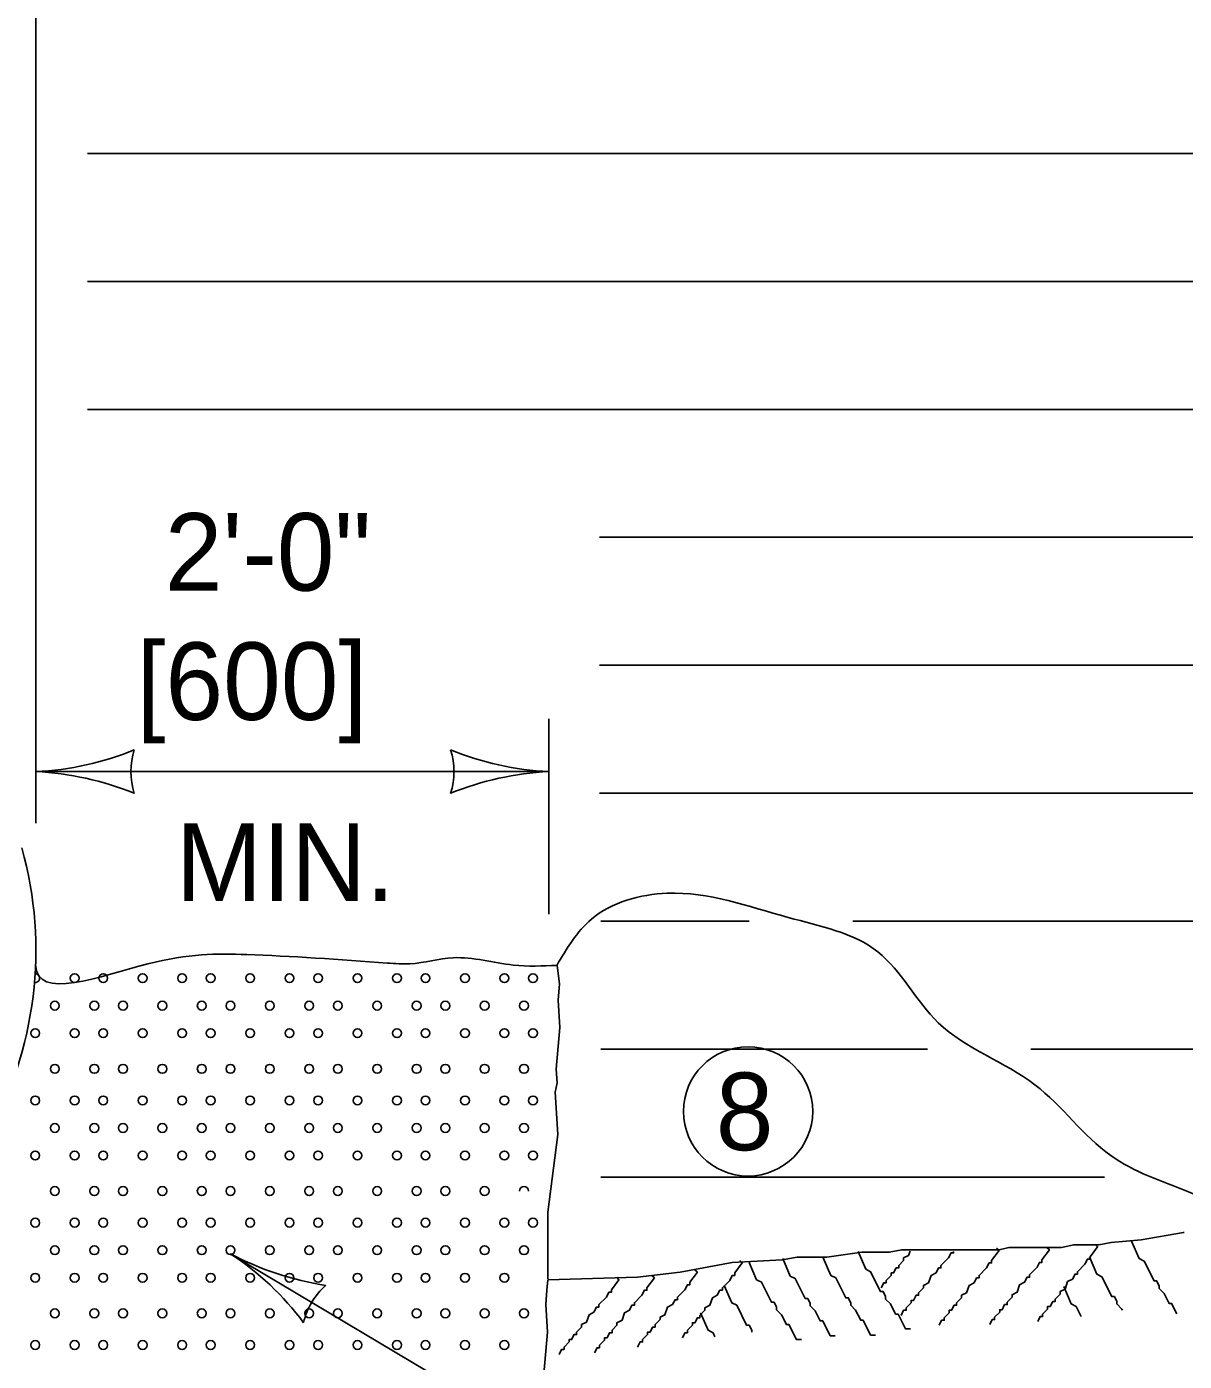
# Model space of a CAD drawing. Extents: x 49991.4 to 50021, y 49987.6 to 50011.4.
# Drawn here: x 50013.69 to 50014.585, y 50002.057 to 50003.09 of the extents above; entities that cross this region are included whole.
import ezdxf

# ---------------------------------------------------------------- set-up
doc = ezdxf.new("R2010")
doc.units = 0
for name, color, linetype in [('Level 1', 7, 'Continuous'), ('Level 2', 7, 'Continuous'), ('Level 3', 7, 'Continuous')]:
    doc.layers.add(name, color=color, linetype=linetype)

msp = doc.modelspace()

# ---------------------------------------------------------------- linework, layer by layer
at = {"layer": 'Level 1'}
for p, q in [((50016.3368, 50002.9916), (50013.737, 50002.9916)), ((50013.737, 50002.8926), (50016.3368, 50002.8926)), ((50013.737, 50002.7936), (50016.3368, 50002.7936)), ((50014.133, 50002.6946), (50016.3368, 50002.6946)), ((50014.133, 50002.5956), (50016.3368, 50002.5956)), ((50014.133, 50002.4966), (50016.3368, 50002.4966)), ((50014.1341, 50002.3976), (50014.2488, 50002.3976)), ((50014.3288, 50002.3976), (50016.3368, 50002.3976)), ((50014.1341, 50002.2986), (50014.3866, 50002.2986)), ((50014.4666, 50002.2986), (50016.3368, 50002.2986)), ((50014.1341, 50002.1996), (50014.5237, 50002.1996))]:
    msp.add_line(p, q, dxfattribs=at)
for points in [[(50014.0931, 50002.1208), (50014.093, 50002.1725), (50014.1007, 50002.2325), (50014.0986, 50002.2653), (50014.1002, 50002.2725), (50014.0994, 50002.2832), (50014.1024, 50002.3154), (50014.101, 50002.3366), (50014.1019, 50002.349), (50014.1002, 50002.3634)], [(50014.093, 50002.1201), (50014.1624, 50002.1221), (50014.1953, 50002.126), (50014.2357, 50002.1336), (50014.2743, 50002.1356), (50014.2858, 50002.1375), (50014.3089, 50002.1375), (50014.336, 50002.1414), (50014.3571, 50002.1414), (50014.3668, 50002.1433), (50014.4111, 50002.1433), (50014.442, 50002.1433), (50014.4497, 50002.1452), (50014.4902, 50002.1452), (50014.4998, 50002.1472), (50014.5191, 50002.1472), (50014.5287, 50002.1491), (50014.5519, 50002.151), (50014.5846, 50002.1568), (50014.5852, 50002.1568)], [(50014.3331, 50002.1419), (50014.3389, 50002.1284), (50014.3427, 50002.1264), (50014.3504, 50002.111), (50014.3524, 50002.111), (50014.3543, 50002.1071), (50014.3543, 50002.1052), (50014.3581, 50002.1014), (50014.362, 50002.0936), (50014.3639, 50002.0936), (50014.3697, 50002.0821), (50014.3736, 50002.0821)], [(50014.3732, 50002.1422), (50014.3721, 50002.139), (50014.3682, 50002.137), (50014.3682, 50002.1351), (50014.3644, 50002.1313), (50014.3644, 50002.1293), (50014.3625, 50002.1293), (50014.3605, 50002.1255), (50014.3586, 50002.1255), (50014.3586, 50002.1235), (50014.3548, 50002.1197), (50014.3548, 50002.1178), (50014.3528, 50002.1178), (50014.3509, 50002.1139)], [(50014.4068, 50002.1419), (50014.4068, 50002.1409), (50014.4049, 50002.1409), (50014.403, 50002.137), (50014.3971, 50002.1313), (50014.3971, 50002.1293), (50014.3952, 50002.1293), (50014.3933, 50002.1255), (50014.3895, 50002.1235), (50014.3875, 50002.1178), (50014.3837, 50002.1158), (50014.3837, 50002.1139), (50014.3798, 50002.1101), (50014.3798, 50002.1081), (50014.3779, 50002.1081), (50014.3759, 50002.1042), (50014.374, 50002.1042), (50014.374, 50002.1023), (50014.3702, 50002.0985), (50014.3702, 50002.0965), (50014.3682, 50002.0965), (50014.3663, 50002.0926)], [(50014.4401, 50002.1447), (50014.442, 50002.1428), (50014.4362, 50002.1351), (50014.4362, 50002.1332), (50014.4343, 50002.1332), (50014.4324, 50002.1293), (50014.4266, 50002.1235), (50014.4266, 50002.1216), (50014.4247, 50002.1216), (50014.4227, 50002.1178), (50014.4189, 50002.1158), (50014.4169, 50002.1101), (50014.4131, 50002.1081), (50014.4131, 50002.1062), (50014.4092, 50002.1023), (50014.4092, 50002.1004), (50014.4073, 50002.1004), (50014.4053, 50002.0965), (50014.4034, 50002.0965), (50014.4034, 50002.0946), (50014.3996, 50002.0907), (50014.3996, 50002.0888), (50014.3976, 50002.0888), (50014.3957, 50002.085)], [(50014.4791, 50002.1452), (50014.481, 50002.1433), (50014.4752, 50002.1356), (50014.4752, 50002.1336), (50014.4733, 50002.1336), (50014.4714, 50002.1298), (50014.4656, 50002.124), (50014.4656, 50002.1221), (50014.4637, 50002.1221), (50014.4618, 50002.1182), (50014.4579, 50002.1163), (50014.456, 50002.1105), (50014.4521, 50002.1086), (50014.4521, 50002.1067), (50014.4483, 50002.1028), (50014.4483, 50002.1009), (50014.4463, 50002.1009), (50014.4444, 50002.097), (50014.4425, 50002.097), (50014.4425, 50002.0951), (50014.4386, 50002.0913), (50014.4386, 50002.0893), (50014.4367, 50002.0893), (50014.4348, 50002.0854)], [(50014.5162, 50002.1476), (50014.5182, 50002.1457), (50014.5124, 50002.138), (50014.5124, 50002.1361), (50014.5104, 50002.1361), (50014.5085, 50002.1322), (50014.5027, 50002.1264), (50014.5027, 50002.1245), (50014.5008, 50002.1245), (50014.4988, 50002.1206), (50014.495, 50002.1187), (50014.4931, 50002.1129), (50014.4892, 50002.111), (50014.4892, 50002.1091), (50014.4853, 50002.1052), (50014.4853, 50002.1033), (50014.4835, 50002.1033), (50014.4815, 50002.0995), (50014.4796, 50002.0995), (50014.4796, 50002.0975), (50014.4757, 50002.0936), (50014.4757, 50002.0917), (50014.4738, 50002.0917), (50014.4719, 50002.0878)], [(50014.5446, 50002.15), (50014.5505, 50002.1365), (50014.5543, 50002.1346), (50014.562, 50002.1192), (50014.5639, 50002.1192), (50014.5658, 50002.1154), (50014.5658, 50002.1134), (50014.5697, 50002.1096), (50014.5736, 50002.1019), (50014.5755, 50002.1019), (50014.5795, 50002.0937)], [(50014.2415, 50002.1351), (50014.2434, 50002.1332), (50014.2376, 50002.1255), (50014.2376, 50002.1235), (50014.2357, 50002.1235), (50014.2338, 50002.1197), (50014.228, 50002.1139), (50014.228, 50002.112), (50014.2261, 50002.112), (50014.2241, 50002.1081), (50014.2203, 50002.1062), (50014.2183, 50002.1004), (50014.2145, 50002.0985), (50014.2145, 50002.0965), (50014.2106, 50002.0926), (50014.2106, 50002.0907), (50014.2087, 50002.0907), (50014.2068, 50002.0869), (50014.2049, 50002.0869), (50014.2049, 50002.085), (50014.201, 50002.0811), (50014.201, 50002.0792), (50014.1991, 50002.0792), (50014.1972, 50002.0753)], [(50014.2487, 50002.1336), (50014.2545, 50002.1201), (50014.2583, 50002.1182), (50014.2661, 50002.1028), (50014.268, 50002.1028), (50014.2699, 50002.099), (50014.2699, 50002.097), (50014.2738, 50002.0931), (50014.2776, 50002.0854), (50014.2795, 50002.0854), (50014.2853, 50002.0739), (50014.2892, 50002.0739)], [(50014.2747, 50002.1365), (50014.2805, 50002.123), (50014.2844, 50002.1211), (50014.2921, 50002.1057), (50014.294, 50002.1057), (50014.296, 50002.1019), (50014.296, 50002.0999), (50014.2998, 50002.0961), (50014.3037, 50002.0883), (50014.3056, 50002.0883), (50014.3114, 50002.0768), (50014.3153, 50002.0768)], [(50014.3061, 50002.137), (50014.3119, 50002.1235), (50014.3157, 50002.1216), (50014.3235, 50002.1062), (50014.3254, 50002.1062), (50014.3273, 50002.1023), (50014.3273, 50002.1004), (50014.3311, 50002.0965), (50014.335, 50002.0888), (50014.3369, 50002.0888), (50014.3427, 50002.0773), (50014.3465, 50002.0773)], [(50014.5119, 50002.138), (50014.5176, 50002.1245), (50014.5215, 50002.1225), (50014.5292, 50002.1071), (50014.5312, 50002.1071), (50014.5331, 50002.1033), (50014.5331, 50002.1014), (50014.5369, 50002.0975), (50014.5374, 50002.0965)], [(50014.0834, 50001.8856), (50014.0834, 50001.8926), (50014.0854, 50001.8926), (50014.0834, 50001.937), (50014.0911, 50001.9968), (50014.0891, 50002.0295), (50014.0907, 50002.0368), (50014.0899, 50002.0474), (50014.0928, 50002.0797), (50014.0915, 50002.1009), (50014.0923, 50002.1122), (50014.093, 50002.1201)], [(50014.1461, 50002.1221), (50014.148, 50002.1201), (50014.1422, 50002.1124), (50014.1422, 50002.1105), (50014.1403, 50002.1105), (50014.1383, 50002.1067), (50014.1325, 50002.1009), (50014.1325, 50002.099), (50014.1306, 50002.099), (50014.1287, 50002.0951), (50014.1249, 50002.0931), (50014.1229, 50002.0874), (50014.119, 50002.0854), (50014.119, 50002.0835), (50014.1152, 50002.0797), (50014.1152, 50002.0777), (50014.1133, 50002.0777), (50014.1114, 50002.0739), (50014.1094, 50002.0739), (50014.1094, 50002.072), (50014.1056, 50002.0681), (50014.1056, 50002.0662), (50014.1036, 50002.0662), (50014.1017, 50002.0623)], [(50014.1735, 50002.1235), (50014.1755, 50002.1216), (50014.1697, 50002.1139), (50014.1697, 50002.112), (50014.1677, 50002.112), (50014.1658, 50002.1081), (50014.16, 50002.1023), (50014.16, 50002.1004), (50014.1581, 50002.1004), (50014.1562, 50002.0965), (50014.1523, 50002.0946), (50014.1504, 50002.0888), (50014.1465, 50002.0869), (50014.1465, 50002.085), (50014.1427, 50002.0811), (50014.1427, 50002.0792), (50014.1407, 50002.0792), (50014.1388, 50002.0753), (50014.1369, 50002.0753), (50014.1369, 50002.0734), (50014.133, 50002.0696), (50014.133, 50002.0676), (50014.1311, 50002.0676), (50014.1292, 50002.0637)], [(50014.2068, 50002.1279), (50014.2087, 50002.126), (50014.2029, 50002.1182), (50014.2029, 50002.1163), (50014.201, 50002.1163), (50014.1991, 50002.1124), (50014.1933, 50002.1067), (50014.1933, 50002.1047), (50014.1914, 50002.1047), (50014.1894, 50002.1009), (50014.1856, 50002.099), (50014.1836, 50002.0931), (50014.1798, 50002.0912), (50014.1798, 50002.0893), (50014.1759, 50002.0854), (50014.1759, 50002.0835), (50014.174, 50002.0835), (50014.1721, 50002.0797), (50014.1701, 50002.0797), (50014.1701, 50002.0777), (50014.1663, 50002.0739), (50014.1663, 50002.072), (50014.1644, 50002.072), (50014.1624, 50002.0681)], [(50014.2294, 50002.1158), (50014.2352, 50002.1023), (50014.2391, 50002.1004), (50014.2468, 50002.085), (50014.2487, 50002.085), (50014.2507, 50002.0811), (50014.2507, 50002.0795)], [(50014.4921, 50002.1148), (50014.4979, 50002.1014), (50014.5018, 50002.0994), (50014.5056, 50002.0917)], [(50014.2111, 50002.0946), (50014.2169, 50002.0811), (50014.2208, 50002.0792), (50014.2223, 50002.0761)]]:
    msp.add_lwpolyline(points, dxfattribs=at)
for centre in [(50013.727, 50002.3535), (50013.7491, 50002.3535), (50013.7796, 50002.3535), (50013.8101, 50002.3535), (50013.8322, 50002.3535), (50013.8627, 50002.3535), (50013.8932, 50002.3535), (50013.9153, 50002.3535), (50013.9458, 50002.3535), (50013.9763, 50002.3535), (50013.9984, 50002.3535), (50014.0289, 50002.3535), (50014.0594, 50002.3535), (50014.0815, 50002.3535), (50013.7117, 50002.3322), (50013.7117, 50002.3322), (50013.7422, 50002.3322), (50013.7644, 50002.3322), (50013.7948, 50002.3322), (50013.7948, 50002.3322), (50013.8253, 50002.3322), (50013.8475, 50002.3322), (50013.8779, 50002.3322), (50013.8779, 50002.3322), (50013.9084, 50002.3322), (50013.9306, 50002.3322), (50013.961, 50002.3322), (50013.961, 50002.3322), (50013.9915, 50002.3322), (50014.0137, 50002.3322), (50014.0441, 50002.3322), (50014.0441, 50002.3322), (50014.0746, 50002.3322), (50013.6965, 50002.3109), (50013.727, 50002.3109), (50013.7491, 50002.3109), (50013.7796, 50002.3109), (50013.8101, 50002.3109), (50013.8322, 50002.3109), (50013.8627, 50002.3109), (50013.8932, 50002.3109), (50013.9153, 50002.3109), (50013.9458, 50002.3109), (50013.9763, 50002.3109), (50013.9984, 50002.3109), (50014.0289, 50002.3109), (50014.0594, 50002.3109), (50014.0815, 50002.3109), (50013.6965, 50002.2589), (50013.727, 50002.2589), (50013.7491, 50002.2589), (50013.7796, 50002.2589), (50013.8101, 50002.2589), (50013.8322, 50002.2589), (50013.8627, 50002.2589), (50013.8932, 50002.2589), (50013.9153, 50002.2589), (50013.9458, 50002.2589), (50013.9763, 50002.2589), (50013.9984, 50002.2589), (50014.0289, 50002.2589), (50014.0594, 50002.2589), (50014.0815, 50002.2589), (50013.7117, 50002.2376), (50013.7117, 50002.2376), (50013.7422, 50002.2376), (50013.7644, 50002.2376), (50013.7948, 50002.2376), (50013.7948, 50002.2376), (50013.8253, 50002.2376), (50013.8475, 50002.2376), (50013.8779, 50002.2376), (50013.8779, 50002.2376), (50013.9084, 50002.2376), (50013.9306, 50002.2376), (50013.961, 50002.2376), (50013.961, 50002.2376), (50013.9915, 50002.2376), (50014.0137, 50002.2376), (50014.0441, 50002.2376), (50014.0441, 50002.2376), (50014.0746, 50002.2376), (50013.6965, 50002.2163), (50013.727, 50002.2163), (50013.7491, 50002.2163), (50013.7796, 50002.2163), (50013.8101, 50002.2163), (50013.8322, 50002.2163), (50013.8627, 50002.2163), (50013.8932, 50002.2163), (50013.9153, 50002.2163), (50013.9458, 50002.2163), (50013.9763, 50002.2163), (50013.9984, 50002.2163), (50014.0289, 50002.2163), (50014.0594, 50002.2163), (50014.0815, 50002.2163), (50013.6965, 50002.1643), (50013.727, 50002.1643), (50013.7491, 50002.1643), (50013.7796, 50002.1643), (50013.8101, 50002.1643), (50013.8322, 50002.1643), (50013.8627, 50002.1643), (50013.8932, 50002.1643), (50013.9153, 50002.1643), (50013.9458, 50002.1643), (50013.9763, 50002.1643), (50013.9984, 50002.1643), (50014.0289, 50002.1643), (50014.0594, 50002.1643), (50014.0815, 50002.1643), (50013.7117, 50002.143), (50013.7117, 50002.143), (50013.7422, 50002.143), (50013.7644, 50002.143), (50013.7948, 50002.143), (50013.7948, 50002.143), (50013.8253, 50002.143), (50013.8475, 50002.143), (50013.8779, 50002.143), (50013.8779, 50002.143), (50013.9084, 50002.143), (50013.9306, 50002.143), (50013.961, 50002.143), (50013.961, 50002.143), (50013.9915, 50002.143), (50014.0137, 50002.143), (50014.0441, 50002.143), (50014.0441, 50002.143), (50014.0746, 50002.143), (50013.6965, 50002.1217), (50013.727, 50002.1217), (50013.7491, 50002.1217), (50013.7796, 50002.1217), (50013.8101, 50002.1217), (50013.8322, 50002.1217), (50013.8627, 50002.1217), (50013.8932, 50002.1217), (50013.9153, 50002.1217), (50013.9458, 50002.1217), (50013.9763, 50002.1217), (50013.9984, 50002.1217), (50014.0289, 50002.1217), (50014.0594, 50002.1217), (50013.6965, 50002.0697), (50013.727, 50002.0697), (50013.7491, 50002.0697), (50013.7796, 50002.0697), (50013.8101, 50002.0697), (50013.8322, 50002.0697), (50013.8627, 50002.0697), (50013.8932, 50002.0697), (50013.9153, 50002.0697), (50013.9458, 50002.0697), (50013.9763, 50002.0697), (50013.9984, 50002.0697), (50014.0289, 50002.0697), (50014.0594, 50002.0697)]:
    msp.add_circle(centre, 0.00341, dxfattribs=at)
for centre, radius, start, end in [((50013.4024, 50002.3751), 0.2946, 285.2566, 15.6031), ((50013.6965, 50002.3535), 0.00341, 261.2712, 90.3416), ((50013.7117, 50002.2834), 0.00341, 0, 180), ((50013.7422, 50002.2834), 0.00341, 0, 180), ((50013.7644, 50002.2834), 0.00341, 0, 180), ((50013.7948, 50002.2834), 0.00341, 0, 180), ((50013.8253, 50002.2834), 0.00341, 0, 180), ((50013.8475, 50002.2834), 0.00341, 0, 180), ((50013.8779, 50002.2834), 0.00341, 0, 180), ((50013.9084, 50002.2834), 0.00341, 0, 180), ((50013.9306, 50002.2834), 0.00341, 0, 180), ((50013.961, 50002.2834), 0.00341, 0, 180), ((50013.9915, 50002.2834), 0.00341, 0, 180), ((50014.0137, 50002.2834), 0.00341, 0, 180), ((50014.0441, 50002.2834), 0.00341, 0, 180), ((50014.0746, 50002.2834), 0.00341, 0, 180), ((50013.7117, 50002.2833), 0.00341, 180, 0), ((50013.7117, 50002.2833), 0.00341, 180, 0), ((50013.7422, 50002.2833), 0.00341, 180, 0), ((50013.7644, 50002.2833), 0.00341, 180, 0), ((50013.7948, 50002.2833), 0.00341, 180, 0), ((50013.7948, 50002.2833), 0.00341, 180, 0), ((50013.8253, 50002.2833), 0.00341, 180, 0), ((50013.8475, 50002.2833), 0.00341, 180, 0), ((50013.8779, 50002.2833), 0.00341, 180, 0), ((50013.8779, 50002.2833), 0.00341, 180, 0), ((50013.9084, 50002.2833), 0.00341, 180, 0), ((50013.9306, 50002.2833), 0.00341, 180, 0), ((50013.961, 50002.2833), 0.00341, 180, 0), ((50013.961, 50002.2833), 0.00341, 180, 0), ((50013.9915, 50002.2833), 0.00341, 180, 0), ((50014.0137, 50002.2833), 0.00341, 180, 0), ((50014.0441, 50002.2833), 0.00341, 180, 0), ((50014.0441, 50002.2833), 0.00341, 180, 0), ((50014.0746, 50002.2833), 0.00341, 180, 0), ((50013.7117, 50002.1888), 0.00341, 0, 180), ((50013.7422, 50002.1888), 0.00341, 0, 180), ((50013.7644, 50002.1888), 0.00341, 0, 180), ((50013.7948, 50002.1888), 0.00341, 0, 180), ((50013.8253, 50002.1888), 0.00341, 0, 180), ((50013.8475, 50002.1888), 0.00341, 0, 180), ((50013.8779, 50002.1888), 0.00341, 0, 180), ((50013.9084, 50002.1888), 0.00341, 0, 180), ((50013.9306, 50002.1888), 0.00341, 0, 180), ((50013.961, 50002.1888), 0.00341, 0, 180), ((50013.9915, 50002.1888), 0.00341, 0, 180), ((50014.0137, 50002.1888), 0.00341, 0, 180), ((50014.0441, 50002.1888), 0.00341, 0, 180), ((50014.0746, 50002.1888), 0.00341, 0, 180), ((50013.7117, 50002.1887), 0.00341, 180, 0), ((50013.7117, 50002.1887), 0.00341, 180, 0), ((50013.7422, 50002.1887), 0.00341, 180, 0), ((50013.7644, 50002.1887), 0.00341, 180, 0), ((50013.7948, 50002.1887), 0.00341, 180, 0), ((50013.7948, 50002.1887), 0.00341, 180, 0), ((50013.8253, 50002.1887), 0.00341, 180, 0), ((50013.8475, 50002.1887), 0.00341, 180, 0), ((50013.8779, 50002.1887), 0.00341, 180, 0), ((50013.8779, 50002.1887), 0.00341, 180, 0), ((50013.9084, 50002.1887), 0.00341, 180, 0), ((50013.9306, 50002.1887), 0.00341, 180, 0), ((50013.961, 50002.1887), 0.00341, 180, 0), ((50013.961, 50002.1887), 0.00341, 180, 0), ((50013.9915, 50002.1887), 0.00341, 180, 0), ((50014.0137, 50002.1887), 0.00341, 180, 0), ((50014.0441, 50002.1887), 0.00341, 180, 0), ((50014.0441, 50002.1887), 0.00341, 180, 0), ((50013.7117, 50002.0942), 0.00341, 0, 180), ((50013.7117, 50002.0941), 0.00341, 180, 0), ((50013.7117, 50002.0941), 0.00341, 180, 0), ((50013.7422, 50002.0942), 0.00341, 0, 180), ((50013.7422, 50002.0941), 0.00341, 180, 0), ((50013.7644, 50002.0942), 0.00341, 0, 180), ((50013.7644, 50002.0941), 0.00341, 180, 0), ((50013.7948, 50002.0942), 0.00341, 0, 180), ((50013.7948, 50002.0941), 0.00341, 180, 0), ((50013.7948, 50002.0941), 0.00341, 180, 0), ((50013.8253, 50002.0942), 0.00341, 0, 180), ((50013.8253, 50002.0941), 0.00341, 180, 0), ((50013.8475, 50002.0942), 0.00341, 0, 180), ((50013.8475, 50002.0941), 0.00341, 180, 0), ((50013.8779, 50002.0942), 0.00341, 0, 180), ((50013.8779, 50002.0941), 0.00341, 180, 0), ((50013.8779, 50002.0941), 0.00341, 180, 0), ((50013.9084, 50002.0942), 0.00341, 0, 180), ((50013.9084, 50002.0941), 0.00341, 180, 0), ((50013.9306, 50002.0942), 0.00341, 0, 180), ((50013.9306, 50002.0941), 0.00341, 180, 0), ((50013.961, 50002.0942), 0.00341, 0, 180), ((50013.961, 50002.0941), 0.00341, 180, 0), ((50013.961, 50002.0941), 0.00341, 180, 0), ((50013.9915, 50002.0942), 0.00341, 0, 180), ((50013.9915, 50002.0941), 0.00341, 180, 0), ((50014.0137, 50002.0942), 0.00341, 0, 180), ((50014.0137, 50002.0941), 0.00341, 180, 0), ((50014.0441, 50002.0942), 0.00341, 0, 180), ((50014.0441, 50002.0941), 0.00341, 180, 0), ((50014.0441, 50002.0941), 0.00341, 180, 0), ((50014.0746, 50002.0942), 0.00341, 0, 180), ((50014.0746, 50002.0941), 0.00341, 180, 0)]:
    msp.add_arc(centre, radius, start, end, dxfattribs=at)
for points in [[(50014.0999, 50002.3633), (50014.1267, 50002.3991), (50014.1854, 50002.4192), (50014.2789, 50002.4005), (50014.3483, 50002.3738), (50014.395, 50002.319), (50014.4698, 50002.271), (50014.5285, 50002.2162), (50014.5886, 50002.1882), (50014.6655, 50002.1536)], [(50013.6968, 50002.3644), (50013.6968, 50002.3641), (50013.7835, 50002.3645), (50013.8601, 50002.3717), (50013.969, 50002.3652), (50013.9863, 50002.3646), (50014.0198, 50002.3693), (50014.0663, 50002.3636), (50014.1002, 50002.3634)]]:
    msp.add_spline(points, degree=3, dxfattribs=at)
at = {"layer": 'Level 2'}
msp.add_circle((50014.2479, 50002.2504), 0.05, dxfattribs=at)
at = {"layer": 'Level 3'}
for p, q in [((50013.697, 50003.4663), (50013.697, 50002.4733)), ((50014.0938, 50002.4031), (50014.0938, 50002.5541)), ((50013.697, 50002.5133), (50014.093, 50002.5133)), ((50013.8474, 50002.1403), (50014.2521, 50001.8991))]:
    msp.add_line(p, q, dxfattribs=at)
for centre, radius, start, end in [((50013.6879, 50002.7355), 0.2223, 272.3605, 292.544), ((50013.8253, 50002.5133), 0.0548, 162.1388, 197.8612), ((50014.103, 50002.7355), 0.2223, 247.456, 267.6395), ((50013.9656, 50002.5133), 0.0548, 342.1388, 17.8612), ((50013.6855, 50002.2806), 0.233, 67.9228, 87.1727), ((50014.1053, 50002.2806), 0.233, 92.8273, 112.0772), ((50013.7258, 50001.9542), 0.2223, 36.6598, 56.8433), ((50013.9567, 50002.3461), 0.233, 242.0311, 261.2809), ((50013.9575, 50002.0747), 0.0548, 131.3426, 167.065)]:
    msp.add_arc(centre, radius, start, end, dxfattribs=at)

# ---------------------------------------------------------------- texts
at = {"layer": 'Level 2'}
for s, p in [('2\'-0"', (50013.7967, 50002.6533)), ('[600]', (50013.7749, 50002.5533)), ('MIN.', (50013.8053, 50002.4133)), ('8', (50014.2229, 50002.2204))]:
    msp.add_text(s, height=0.06, dxfattribs=at).set_placement(p)

doc.saveas('drawing.dxf')
